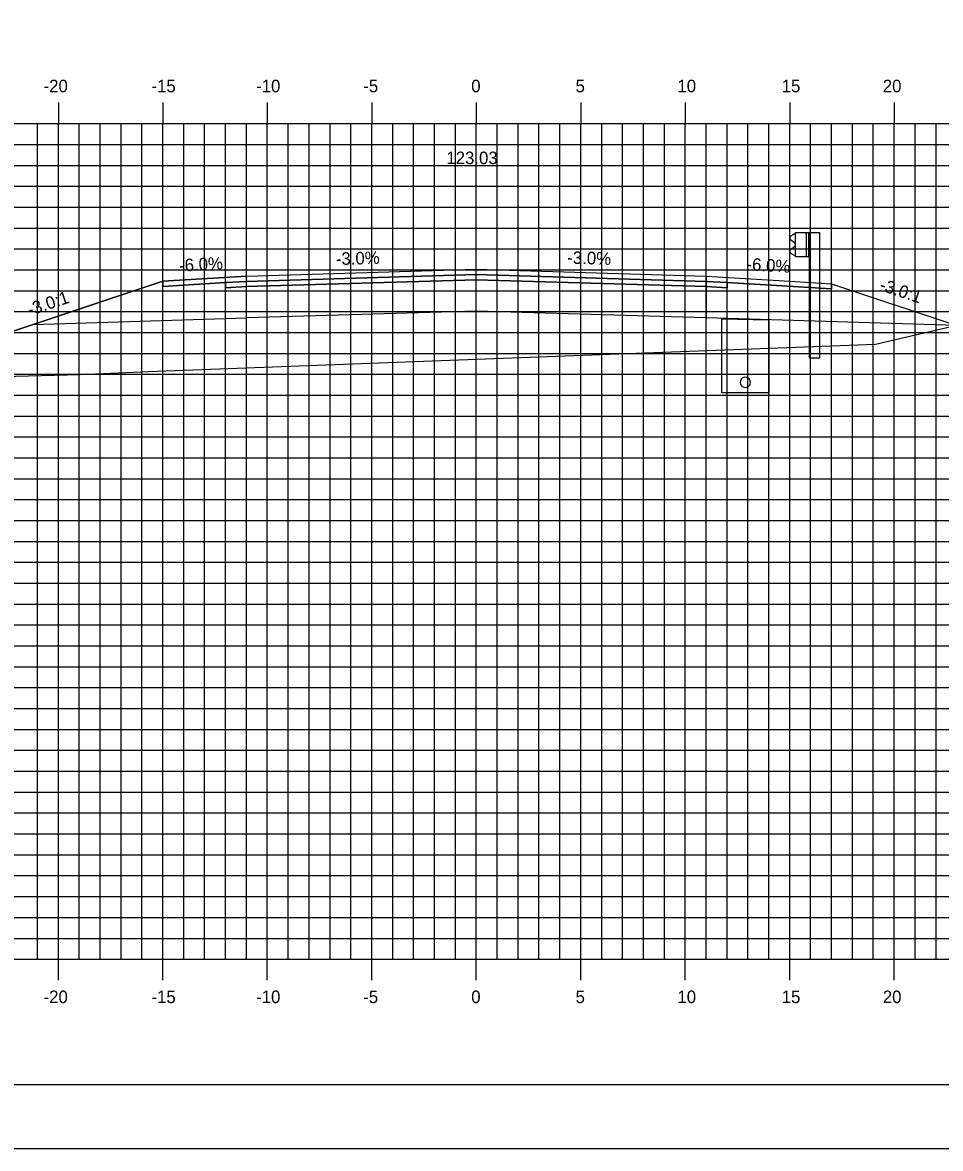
# Model space of a CAD drawing. Extents: x 850598 to 870284, y 366541 to 366651.
# Drawn here: x 853955.5 to 853999.5, y 366541.2 to 366595.1 of the extents above; entities that cross this region are included whole.
import ezdxf

# ---------------------------------------------------------------- set-up
doc = ezdxf.new("R2010")
doc.units = 0
for name, color, linetype in [('ANNOTATION', 7, 'Continuous'), ('BORDER', 7, 'Continuous'), ('D_Drainage_Underdrain', 7, 'Continuous'), ('D_Drainage_Underdrain_06in', 7, 'Continuous'), ('D_Guardrail_Beam_Rt', 7, 'Continuous'), ('D_Roadway_Centerline', 7, 'Continuous'), ('D_Roadway_Centerline_Text', 7, 'Continuous'), ('D_Roadway_Edge_Shoulder', 7, 'Continuous'), ('D_Roadway_Edge_TW', 7, 'Continuous'), ('D_Roadway_Pavement', 7, 'Continuous'), ('D_Roadway_SlopeLines', 7, 'Continuous'), ('D_Roadway_SubGrade', 7, 'Continuous'), ('H_V ANNOTATION', 7, 'Continuous'), ('MAJOR', 7, 'Continuous'), ('MINOR', 7, 'Continuous'), ('PLOT BOUNDARY', 7, 'Continuous'), ('S_Roadway_Centerline', 7, 'Continuous')]:
    doc.layers.add(name, color=color, linetype=linetype)

msp = doc.modelspace()

# ---------------------------------------------------------------- linework, layer by layer
at = {"layer": 'BORDER'}
msp.add_line((853932.245, 366544.225), (854092.245, 366544.225), dxfattribs=at)
at = {"layer": 'D_Drainage_Underdrain'}
msp.add_lwpolyline([(853991.245, 366580.838), (853991.245, 366577.338), (853988.995, 366577.338), (853988.995, 366580.884)], close=True, dxfattribs=at)
at = {"layer": 'D_Drainage_Underdrain_06in'}
msp.add_lwpolyline([(853990.12, 366578.088), (853990.043, 366578.076), (853989.973, 366578.04), (853989.918, 366577.985), (853989.882, 366577.915), (853989.87, 366577.838), (853989.882, 366577.761), (853989.918, 366577.691), (853989.973, 366577.636), (853990.043, 366577.6), (853990.12, 366577.588), (853990.197, 366577.6), (853990.267, 366577.636), (853990.322, 366577.691), (853990.358, 366577.761), (853990.37, 366577.838), (853990.358, 366577.915), (853990.322, 366577.985), (853990.267, 366578.04), (853990.197, 366578.076)], close=True, dxfattribs=at)
at = {"layer": 'D_Guardrail_Beam_Rt'}
for p, q in [((853992.426, 366584.92), (853992.283, 366584.82)), ((853992.283, 366584.677), (853992.478, 366584.54)), ((853992.516, 366584.939), (853992.443, 366584.927)), ((853992.516, 366585.014), (853993.203, 366585.014)), ((853992.516, 366583.847), (853992.516, 366585.014)), ((853993.037, 366585.014), (853993.037, 366583.847)), ((853993.141, 366585.014), (853993.141, 366583.847)), ((853993.203, 366585.014), (853993.674, 366585.014)), ((853993.203, 366585.014), (853993.203, 366583.847)), ((853993.674, 366585.014), (853993.674, 366579.014)), ((853992.478, 366584.321), (853992.283, 366584.185)), ((853992.283, 366584.041), (853992.426, 366583.941)), ((853992.512, 366584.476), (853992.512, 366584.385)), ((853992.443, 366583.935), (853992.516, 366583.922)), ((853993.203, 366583.847), (853992.516, 366583.847)), ((853993.183, 366579.014), (853993.183, 366583.847)), ((853993.183, 366579.014), (853993.674, 366579.014))]:
    msp.add_line(p, q, dxfattribs=at)
for centre, major_axis, start_param, end_param in [((853992.333, 366584.748), (-0.0877, 0), 5.323254, 7.243116), ((853992.45, 366584.886), (-0.0417, 0), 4.886922, 5.323254), ((853992.333, 366584.113), (-0.0877, 0), 5.323254, 7.243116), ((853992.433, 366584.476), (0.0789, 0), 0, 0.959931), ((853992.433, 366584.385), (0.0789, 0), 5.323254, 6.283185), ((853992.45, 366583.975), (-0.0417, 0), 0.959931, 1.396263)]:
    msp.add_ellipse(centre, major_axis=major_axis, ratio=0.995501, start_param=start_param, end_param=end_param, dxfattribs=at)
at = {"layer": 'D_Roadway_Centerline'}
msp.add_lwpolyline([(853947.958, 366577.918), (853952.245, 366579.347), (853956.047, 366580.615), (853962.245, 366582.681), (853966.245, 366582.921), (853977.245, 366583.251), (853988.245, 366582.921), (853992.245, 366582.681), (853994.245, 366582.561), (854000.245, 366580.561), (854044.83, 366568.225), (854056.654, 366564.954), (854066.516, 366562.225), (854070.516, 366562.225)], dxfattribs=at)
at = {"layer": 'D_Roadway_Edge_Shoulder'}
for points in [[(853966.245, 366582.921), (853962.245, 366582.681), (853962.245, 366582.431), (853965.245, 366582.611), (853966.245, 366582.671)], [(853988.245, 366582.921), (853992.245, 366582.681), (853992.245, 366582.681), (853994.245, 366582.561), (853994.245, 366582.311), (853989.245, 366582.611), (853988.245, 366582.671)]]:
    msp.add_lwpolyline(points, close=True, dxfattribs=at)
at = {"layer": 'D_Roadway_Edge_TW'}
msp.add_lwpolyline([(853966.245, 366582.671), (853966.245, 366582.921), (853977.245, 366583.251), (853988.245, 366582.921), (853988.245, 366582.671), (853977.245, 366583.001)], close=True, dxfattribs=at)
at = {"layer": 'D_Roadway_Pavement'}
for points in [[(853966.245, 366582.421), (853966.245, 366582.671), (853977.245, 366583.001), (853988.245, 366582.671), (853988.245, 366582.421), (853977.245, 366582.751)], [(853966.245, 366582.671), (853965.245, 366582.611), (853965.245, 366582.361), (853966.245, 366582.421)], [(853988.245, 366582.671), (853989.245, 366582.611), (853989.245, 366582.361), (853988.245, 366582.421)]]:
    msp.add_lwpolyline(points, close=True, dxfattribs=at)
at = {"layer": 'D_Roadway_SlopeLines'}
msp.add_lwpolyline([(853966.245, 366582.921), (853962.245, 366582.681), (853952.245, 366579.347)], dxfattribs=at)
at = {"layer": 'D_Roadway_SubGrade'}
for points in [[(853966.245, 366582.421), (853965.245, 366582.361), (853965.245, 366582.611), (853962.245, 366582.431), (853962.245, 366582.681), (853956.047, 366580.615), (853966.245, 366580.921)], [(853966.245, 366580.921), (853966.245, 366582.421), (853977.245, 366582.751), (853988.245, 366582.421), (853988.245, 366580.921), (853977.245, 366581.251)], [(853988.245, 366582.421), (853989.245, 366582.361), (853989.245, 366582.611), (853994.245, 366582.311), (853994.245, 366582.561), (854000.245, 366580.561), (853988.245, 366580.921)]]:
    msp.add_lwpolyline(points, close=True, dxfattribs=at)
at = {"layer": 'MAJOR'}
for p, q in [((853957.245, 366591.227), (853957.245, 366590.225)), ((853957.245, 366591.227), (853957.245, 366590.225)), ((853962.245, 366591.227), (853962.245, 366590.225)), ((853962.245, 366591.227), (853962.245, 366590.225)), ((853967.245, 366591.227), (853967.245, 366590.225)), ((853967.245, 366591.227), (853967.245, 366590.225)), ((853972.245, 366591.227), (853972.245, 366590.225)), ((853972.245, 366591.227), (853972.245, 366590.225)), ((853977.245, 366591.227), (853977.245, 366590.225)), ((853977.245, 366591.227), (853977.245, 366590.225)), ((853982.245, 366591.227), (853982.245, 366590.225)), ((853982.245, 366591.227), (853982.245, 366590.225)), ((853987.245, 366591.227), (853987.245, 366590.225)), ((853987.245, 366591.227), (853987.245, 366590.225)), ((853992.245, 366591.227), (853992.245, 366590.225)), ((853992.245, 366591.227), (853992.245, 366590.225)), ((853997.245, 366591.227), (853997.245, 366590.225)), ((853997.245, 366591.227), (853997.245, 366590.225)), ((853937.245, 366590.225), (854077.245, 366590.225)), ((853937.245, 366590.225), (854077.245, 366590.225)), ((853937.245, 366590.225), (854077.245, 366590.225)), ((853937.245, 366590.225), (854077.245, 366590.225)), ((853957.245, 366550.225), (853957.245, 366590.225)), ((853957.245, 366550.225), (853957.245, 366590.225)), ((853962.245, 366550.225), (853962.245, 366590.225)), ((853962.245, 366550.225), (853962.245, 366590.225)), ((853967.245, 366550.225), (853967.245, 366590.225)), ((853967.245, 366550.225), (853967.245, 366590.225)), ((853972.245, 366550.225), (853972.245, 366590.225)), ((853972.245, 366550.225), (853972.245, 366590.225)), ((853977.245, 366550.225), (853977.245, 366590.225)), ((853977.245, 366550.225), (853977.245, 366590.225)), ((853982.245, 366550.225), (853982.245, 366590.225)), ((853982.245, 366550.225), (853982.245, 366590.225)), ((853987.245, 366550.225), (853987.245, 366590.225)), ((853987.245, 366550.225), (853987.245, 366590.225)), ((853992.245, 366550.225), (853992.245, 366590.225)), ((853992.245, 366550.225), (853992.245, 366590.225)), ((853997.245, 366550.225), (853997.245, 366590.225)), ((853997.245, 366550.225), (853997.245, 366590.225)), ((853937.245, 366585.225), (854077.245, 366585.225)), ((853937.245, 366585.225), (854077.245, 366585.225)), ((853937.245, 366580.225), (854077.245, 366580.225)), ((853937.245, 366580.225), (854077.245, 366580.225)), ((853937.245, 366575.225), (854077.245, 366575.225)), ((853937.245, 366575.225), (854077.245, 366575.225)), ((853937.245, 366570.225), (854077.245, 366570.225)), ((853937.245, 366570.225), (854077.245, 366570.225)), ((853937.245, 366565.225), (854077.245, 366565.225)), ((853937.245, 366565.225), (854077.245, 366565.225)), ((853937.245, 366560.225), (854077.245, 366560.225)), ((853937.245, 366560.225), (854077.245, 366560.225)), ((853937.245, 366555.225), (854077.245, 366555.225)), ((853937.245, 366555.225), (854077.245, 366555.225)), ((853937.245, 366550.225), (854077.245, 366550.225)), ((853937.245, 366550.225), (854077.245, 366550.225)), ((853937.245, 366550.225), (854077.245, 366550.225)), ((853937.245, 366550.225), (854077.245, 366550.225)), ((853957.245, 366549.223), (853957.245, 366550.225)), ((853957.245, 366549.223), (853957.245, 366550.225)), ((853962.245, 366549.223), (853962.245, 366550.225)), ((853962.245, 366549.223), (853962.245, 366550.225)), ((853967.245, 366549.223), (853967.245, 366550.225)), ((853967.245, 366549.223), (853967.245, 366550.225)), ((853972.245, 366549.223), (853972.245, 366550.225)), ((853972.245, 366549.223), (853972.245, 366550.225)), ((853977.245, 366549.223), (853977.245, 366550.225)), ((853977.245, 366549.223), (853977.245, 366550.225)), ((853982.245, 366549.223), (853982.245, 366550.225)), ((853982.245, 366549.223), (853982.245, 366550.225)), ((853987.245, 366549.223), (853987.245, 366550.225)), ((853987.245, 366549.223), (853987.245, 366550.225)), ((853992.245, 366549.223), (853992.245, 366550.225)), ((853992.245, 366549.223), (853992.245, 366550.225)), ((853997.245, 366549.223), (853997.245, 366550.225)), ((853997.245, 366549.223), (853997.245, 366550.225))]:
    msp.add_line(p, q, dxfattribs=at)
at = {"layer": 'MINOR'}
for p, q in [((853956.245, 366550.225), (853956.245, 366590.225)), ((853956.245, 366550.225), (853956.245, 366590.225)), ((853958.245, 366550.225), (853958.245, 366590.225)), ((853958.245, 366550.225), (853958.245, 366590.225)), ((853959.245, 366550.225), (853959.245, 366590.225)), ((853959.245, 366550.225), (853959.245, 366590.225)), ((853960.245, 366550.225), (853960.245, 366590.225)), ((853960.245, 366550.225), (853960.245, 366590.225)), ((853961.245, 366550.225), (853961.245, 366590.225)), ((853961.245, 366550.225), (853961.245, 366590.225)), ((853963.245, 366550.225), (853963.245, 366590.225)), ((853963.245, 366550.225), (853963.245, 366590.225)), ((853964.245, 366550.225), (853964.245, 366590.225)), ((853964.245, 366550.225), (853964.245, 366590.225)), ((853965.245, 366550.225), (853965.245, 366590.225)), ((853965.245, 366550.225), (853965.245, 366590.225)), ((853966.245, 366550.225), (853966.245, 366590.225)), ((853966.245, 366550.225), (853966.245, 366590.225)), ((853968.245, 366550.225), (853968.245, 366590.225)), ((853968.245, 366550.225), (853968.245, 366590.225)), ((853969.245, 366550.225), (853969.245, 366590.225)), ((853969.245, 366550.225), (853969.245, 366590.225)), ((853970.245, 366550.225), (853970.245, 366590.225)), ((853970.245, 366550.225), (853970.245, 366590.225)), ((853971.245, 366550.225), (853971.245, 366590.225)), ((853971.245, 366550.225), (853971.245, 366590.225)), ((853973.245, 366550.225), (853973.245, 366590.225)), ((853973.245, 366550.225), (853973.245, 366590.225)), ((853974.245, 366550.225), (853974.245, 366590.225)), ((853974.245, 366550.225), (853974.245, 366590.225)), ((853975.245, 366550.225), (853975.245, 366590.225)), ((853975.245, 366550.225), (853975.245, 366590.225)), ((853976.245, 366550.225), (853976.245, 366590.225)), ((853976.245, 366550.225), (853976.245, 366590.225)), ((853978.245, 366550.225), (853978.245, 366590.225)), ((853978.245, 366550.225), (853978.245, 366590.225)), ((853979.245, 366550.225), (853979.245, 366590.225)), ((853979.245, 366550.225), (853979.245, 366590.225)), ((853980.245, 366550.225), (853980.245, 366590.225)), ((853980.245, 366550.225), (853980.245, 366590.225)), ((853981.245, 366550.225), (853981.245, 366590.225)), ((853981.245, 366550.225), (853981.245, 366590.225)), ((853983.245, 366550.225), (853983.245, 366590.225)), ((853983.245, 366550.225), (853983.245, 366590.225)), ((853984.245, 366550.225), (853984.245, 366590.225)), ((853984.245, 366550.225), (853984.245, 366590.225)), ((853985.245, 366550.225), (853985.245, 366590.225)), ((853985.245, 366550.225), (853985.245, 366590.225)), ((853986.245, 366550.225), (853986.245, 366590.225)), ((853986.245, 366550.225), (853986.245, 366590.225)), ((853988.245, 366550.225), (853988.245, 366590.225)), ((853988.245, 366550.225), (853988.245, 366590.225)), ((853989.245, 366550.225), (853989.245, 366590.225)), ((853989.245, 366550.225), (853989.245, 366590.225)), ((853990.245, 366550.225), (853990.245, 366590.225)), ((853990.245, 366550.225), (853990.245, 366590.225)), ((853991.245, 366550.225), (853991.245, 366590.225)), ((853991.245, 366550.225), (853991.245, 366590.225)), ((853993.245, 366550.225), (853993.245, 366590.225)), ((853993.245, 366550.225), (853993.245, 366590.225)), ((853994.245, 366550.225), (853994.245, 366590.225)), ((853994.245, 366550.225), (853994.245, 366590.225)), ((853995.245, 366550.225), (853995.245, 366590.225)), ((853995.245, 366550.225), (853995.245, 366590.225)), ((853996.245, 366550.225), (853996.245, 366590.225)), ((853996.245, 366550.225), (853996.245, 366590.225)), ((853998.245, 366550.225), (853998.245, 366590.225)), ((853998.245, 366550.225), (853998.245, 366590.225)), ((853999.245, 366550.225), (853999.245, 366590.225)), ((853999.245, 366550.225), (853999.245, 366590.225)), ((853937.245, 366589.225), (854077.245, 366589.225)), ((853937.245, 366589.225), (854077.245, 366589.225)), ((853937.245, 366588.225), (854077.245, 366588.225)), ((853937.245, 366588.225), (854077.245, 366588.225)), ((853937.245, 366587.225), (854077.245, 366587.225)), ((853937.245, 366587.225), (854077.245, 366587.225)), ((853937.245, 366586.225), (854077.245, 366586.225)), ((853937.245, 366586.225), (854077.245, 366586.225)), ((853937.245, 366584.225), (854077.245, 366584.225)), ((853937.245, 366584.225), (854077.245, 366584.225)), ((853937.245, 366583.225), (854077.245, 366583.225)), ((853937.245, 366583.225), (854077.245, 366583.225)), ((853937.245, 366582.225), (854077.245, 366582.225)), ((853937.245, 366582.225), (854077.245, 366582.225)), ((853937.245, 366581.225), (854077.245, 366581.225)), ((853937.245, 366581.225), (854077.245, 366581.225)), ((853937.245, 366579.225), (854077.245, 366579.225)), ((853937.245, 366579.225), (854077.245, 366579.225)), ((853937.245, 366578.225), (854077.245, 366578.225)), ((853937.245, 366578.225), (854077.245, 366578.225)), ((853937.245, 366577.225), (854077.245, 366577.225)), ((853937.245, 366577.225), (854077.245, 366577.225)), ((853937.245, 366576.225), (854077.245, 366576.225)), ((853937.245, 366576.225), (854077.245, 366576.225)), ((853937.245, 366574.225), (854077.245, 366574.225)), ((853937.245, 366574.225), (854077.245, 366574.225)), ((853937.245, 366573.225), (854077.245, 366573.225)), ((853937.245, 366573.225), (854077.245, 366573.225)), ((853937.245, 366572.225), (854077.245, 366572.225)), ((853937.245, 366572.225), (854077.245, 366572.225)), ((853937.245, 366571.225), (854077.245, 366571.225)), ((853937.245, 366571.225), (854077.245, 366571.225)), ((853937.245, 366569.225), (854077.245, 366569.225)), ((853937.245, 366569.225), (854077.245, 366569.225)), ((853937.245, 366568.225), (854077.245, 366568.225)), ((853937.245, 366568.225), (854077.245, 366568.225)), ((853937.245, 366567.225), (854077.245, 366567.225)), ((853937.245, 366567.225), (854077.245, 366567.225)), ((853937.245, 366566.225), (854077.245, 366566.225)), ((853937.245, 366566.225), (854077.245, 366566.225)), ((853937.245, 366564.225), (854077.245, 366564.225)), ((853937.245, 366564.225), (854077.245, 366564.225)), ((853937.245, 366563.225), (854077.245, 366563.225)), ((853937.245, 366563.225), (854077.245, 366563.225)), ((853937.245, 366562.225), (854077.245, 366562.225)), ((853937.245, 366562.225), (854077.245, 366562.225)), ((853937.245, 366561.225), (854077.245, 366561.225)), ((853937.245, 366561.225), (854077.245, 366561.225)), ((853937.245, 366559.225), (854077.245, 366559.225)), ((853937.245, 366559.225), (854077.245, 366559.225)), ((853937.245, 366558.225), (854077.245, 366558.225)), ((853937.245, 366558.225), (854077.245, 366558.225)), ((853937.245, 366557.225), (854077.245, 366557.225)), ((853937.245, 366557.225), (854077.245, 366557.225)), ((853937.245, 366556.225), (854077.245, 366556.225)), ((853937.245, 366556.225), (854077.245, 366556.225)), ((853937.245, 366554.225), (854077.245, 366554.225)), ((853937.245, 366554.225), (854077.245, 366554.225)), ((853937.245, 366553.225), (854077.245, 366553.225)), ((853937.245, 366553.225), (854077.245, 366553.225)), ((853937.245, 366552.225), (854077.245, 366552.225)), ((853937.245, 366552.225), (854077.245, 366552.225)), ((853937.245, 366551.225), (854077.245, 366551.225)), ((853937.245, 366551.225), (854077.245, 366551.225))]:
    msp.add_line(p, q, dxfattribs=at)
at = {"layer": 'PLOT BOUNDARY'}
msp.add_lwpolyline([(853924.152, 366541.166), (854094.152, 366541.166), (854094.152, 366651.166), (853924.152, 366651.166)], close=True, dxfattribs=at)
at = {"layer": 'S_Roadway_Centerline'}
msp.add_lwpolyline([(853937.245, 366577.589), (853953.952, 366578.102), (853958.284, 366578.209), (853961.567, 366578.362), (853996.352, 366579.666), (854000.386, 366580.603), (854005.5, 366581.736), (854007.691, 366582.114), (854010.372, 366582.453), (854017.329, 366582.738), (854025.248, 366583.067), (854032.377, 366582.712), (854039.306, 366582.342), (854040.544, 366582.298), (854041.604, 366582.253), (854042.845, 366581.856), (854043.896, 366581.436), (854062.734, 366566.504), (854063.008, 366566.279), (854063.114, 366566.229), (854077.245, 366558.586)], dxfattribs=at)

# ---------------------------------------------------------------- texts
at = {"layer": 'ANNOTATION'}
for s, rotation, p in [('-3.0%', 1.7184, (853970.533, 366583.45)), ('-3.0%', 358.2816, (853981.593, 366583.521)), ('-6.0%', 3.4336, (853963.042, 366583.13)), ('-6.0%', 356.5664, (853990.162, 366583.207)), ('-3.0:1', 341.5651, (853996.499, 366582.263)), ('-3.0:1', 18.4348, (853955.866, 366581.009))]:
    msp.add_text(s, height=0.6, rotation=rotation, dxfattribs=at).set_placement(p)
at = {"layer": 'D_Roadway_Centerline'}
for s, p in [('C', (853977.24, 366583.251)), ('C', (853977.24, 366583.251)), ('L', (853977.245, 366583.243)), ('L', (853977.245, 366583.243))]:
    msp.add_text(s, height=0.0146, dxfattribs=at).set_placement(p)
at = {"layer": 'D_Roadway_Centerline_Text'}
msp.add_text('123.03', height=0.6, dxfattribs=at).set_placement((853975.814, 366588.283))
at = {"layer": 'H_V ANNOTATION'}
for s, p in [('-20', (853956.539, 366591.725)), ('-15', (853961.702, 366591.725)), ('-10', (853966.71, 366591.725)), ('-5', (853971.836, 366591.725)), ('0', (853977.004, 366591.725)), ('5', (853981.996, 366591.725)), ('10', (853986.87, 366591.725)), ('15', (853991.862, 366591.725)), ('20', (853996.699, 366591.725)), ('-20', (853956.539, 366548.125)), ('-15', (853961.702, 366548.125)), ('-10', (853966.71, 366548.125)), ('-5', (853971.836, 366548.125)), ('0', (853977.004, 366548.125)), ('5', (853981.996, 366548.125)), ('10', (853986.87, 366548.125)), ('15', (853991.862, 366548.125)), ('20', (853996.699, 366548.125))]:
    msp.add_text(s, height=0.6, dxfattribs=at).set_placement(p)

doc.saveas('drawing.dxf')
